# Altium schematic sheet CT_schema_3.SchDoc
size 334 x 183 mm
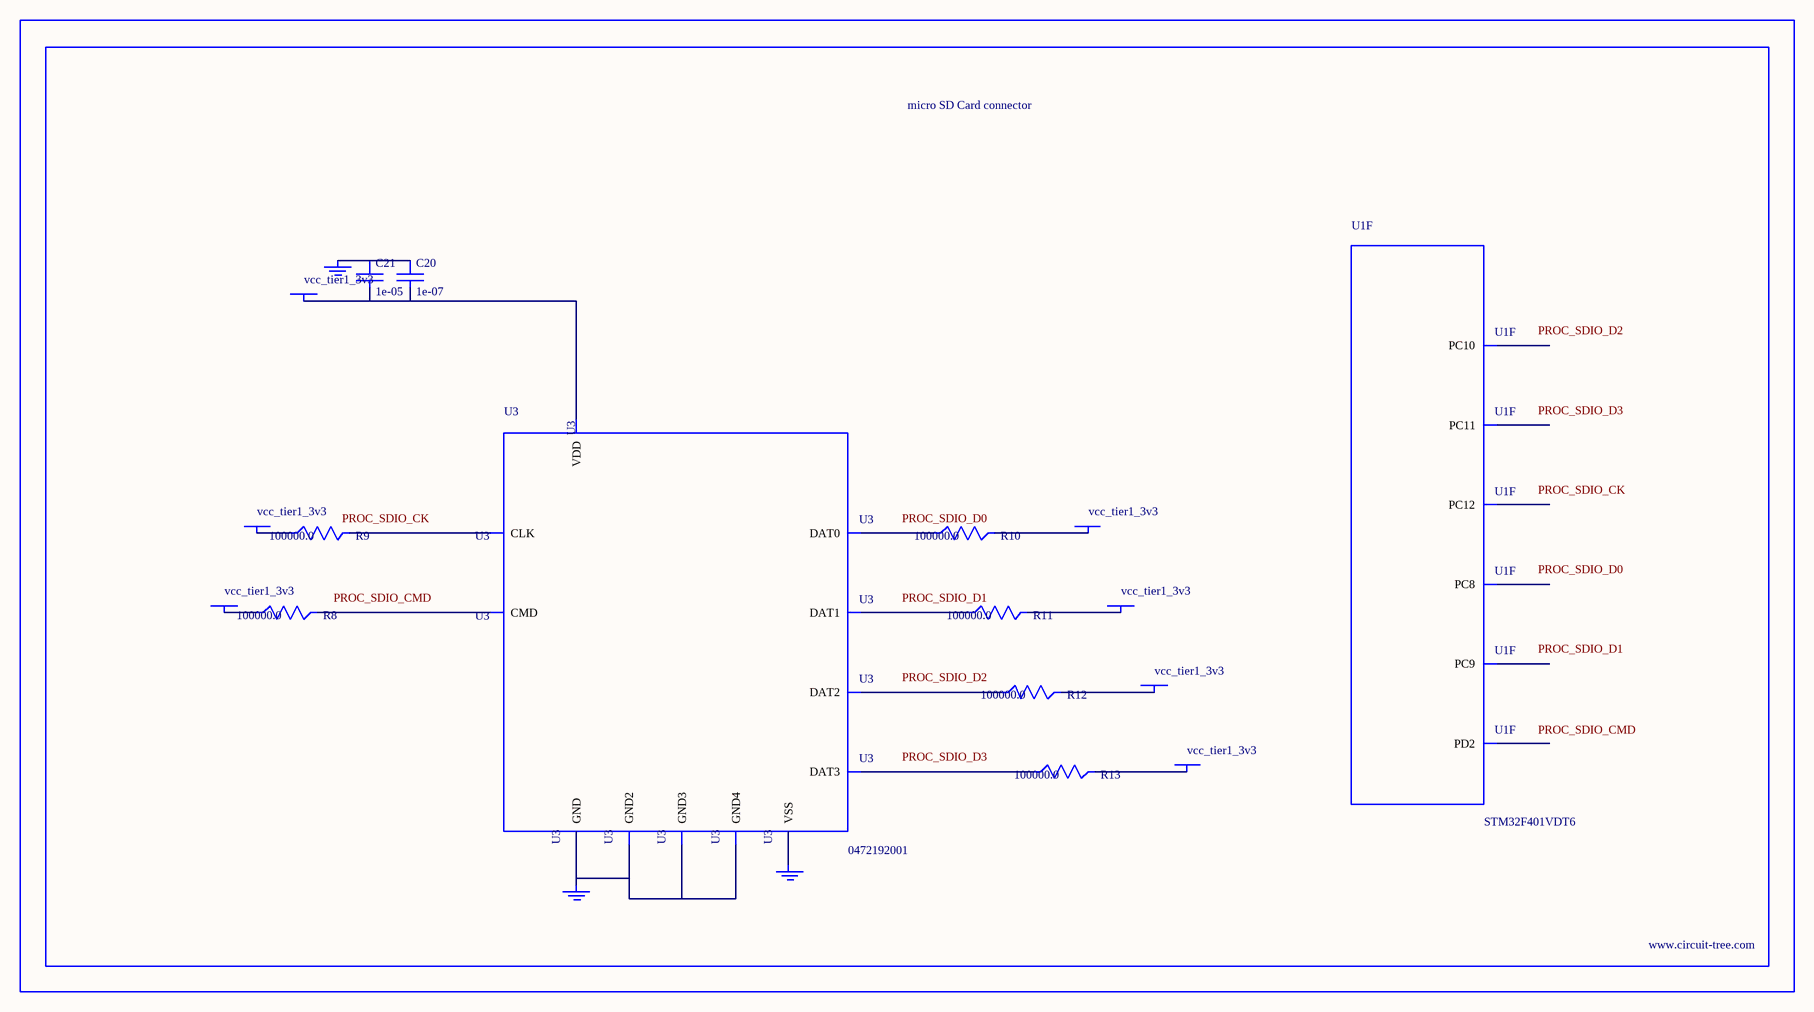
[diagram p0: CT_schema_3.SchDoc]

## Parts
BORDER2  (no value)
C20  1e-07  [C0402]
C21  1e-05  [C0805]
GND_INSTANCE_2_0  (no value)
GND_INSTANCE_2_1  (no value)
GND_INSTANCE_2_2  (no value)
POWER_INSTANCE_2_0  vcc_tier1_3v3
POWER_INSTANCE_2_1  vcc_tier1_3v3
POWER_INSTANCE_2_2  vcc_tier1_3v3
POWER_INSTANCE_2_3  vcc_tier1_3v3
POWER_INSTANCE_2_4  vcc_tier1_3v3
POWER_INSTANCE_2_5  vcc_tier1_3v3
POWER_INSTANCE_2_6  vcc_tier1_3v3
R8  100000.0  [R0603]
R9  100000.0  [R0603]
R10  100000.0  [R0603]
R11  100000.0  [R0603]
R12  100000.0  [R0603]
R13  100000.0  [R0603]
U1  STM32F401VDT6  [LQFP100]  (part F of 10)
U3  0472192001  [MOLEX_47219-2001]

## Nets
NetC20_1: C20.1 C21.1 GND_INSTANCE_2_0.0(GND)
NetC20_2: C20.2 C21.2 POWER_INSTANCE_2_3.0(PWR) U3.4(VDD)
NetGND_INSTANCE_2_1_0: GND_INSTANCE_2_1.0(GND) U3.6(VSS)
NetGND_INSTANCE_2_2_0: GND_INSTANCE_2_2.0(GND) U3.G1(GND) U3.G2(GND2) U3.G3(GND3) U3.G4(GND4)
NetPOWER_INSTANCE_2_0_0: POWER_INSTANCE_2_0.0(PWR) R12.2
NetPOWER_INSTANCE_2_1_0: POWER_INSTANCE_2_1.0(PWR) R13.2
NetPOWER_INSTANCE_2_2_0: POWER_INSTANCE_2_2.0(PWR) R8.1
NetPOWER_INSTANCE_2_4_0: POWER_INSTANCE_2_4.0(PWR) R9.1
NetPOWER_INSTANCE_2_5_0: POWER_INSTANCE_2_5.0(PWR) R10.2
NetPOWER_INSTANCE_2_6_0: POWER_INSTANCE_2_6.0(PWR) R11.2
NetR8_2: R8.2 U3.3(CMD)
NetR9_2: R9.2 U3.5(CLK)
NetR10_1: R10.1 U3.7(DAT0)
NetR11_1: R11.1 U3.8(DAT1)
NetR12_1: R12.1 U3.1(DAT2)
NetR13_1: R13.1 U3.2(DAT3)

Not connected (* = marked no-connect by the designer): U1 65(PC8) 66(PC9) 78(PC10) 79(PC11) 80(PC12) 83(PD2)

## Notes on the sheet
- Labels drawn without touching a wire or pin: PROC_SDIO_CK, PROC_SDIO_CMD, PROC_SDIO_D0, PROC_SDIO_D1, PROC_SDIO_D2, PROC_SDIO_D3

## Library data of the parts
BORDER2 = BORDER_PAGE2
C20 = C0402C104K3RACTU
C21 = C0805C106K8RACTU
GND_INSTANCE_2_0-GND_INSTANCE_2_2 = GND
POWER_INSTANCE_2_0-POWER_INSTANCE_2_6 = PWR
R8-R13 = RC0603JR-07100KL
